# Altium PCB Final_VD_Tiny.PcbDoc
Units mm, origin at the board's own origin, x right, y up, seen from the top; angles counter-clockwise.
Board outline 34.21 x 13.79 mm, 2 copper layers (Top Layer, Bottom Layer), stack 1.671 mm thick; 35 components, 51 nets, 127 pads, 91 vias.
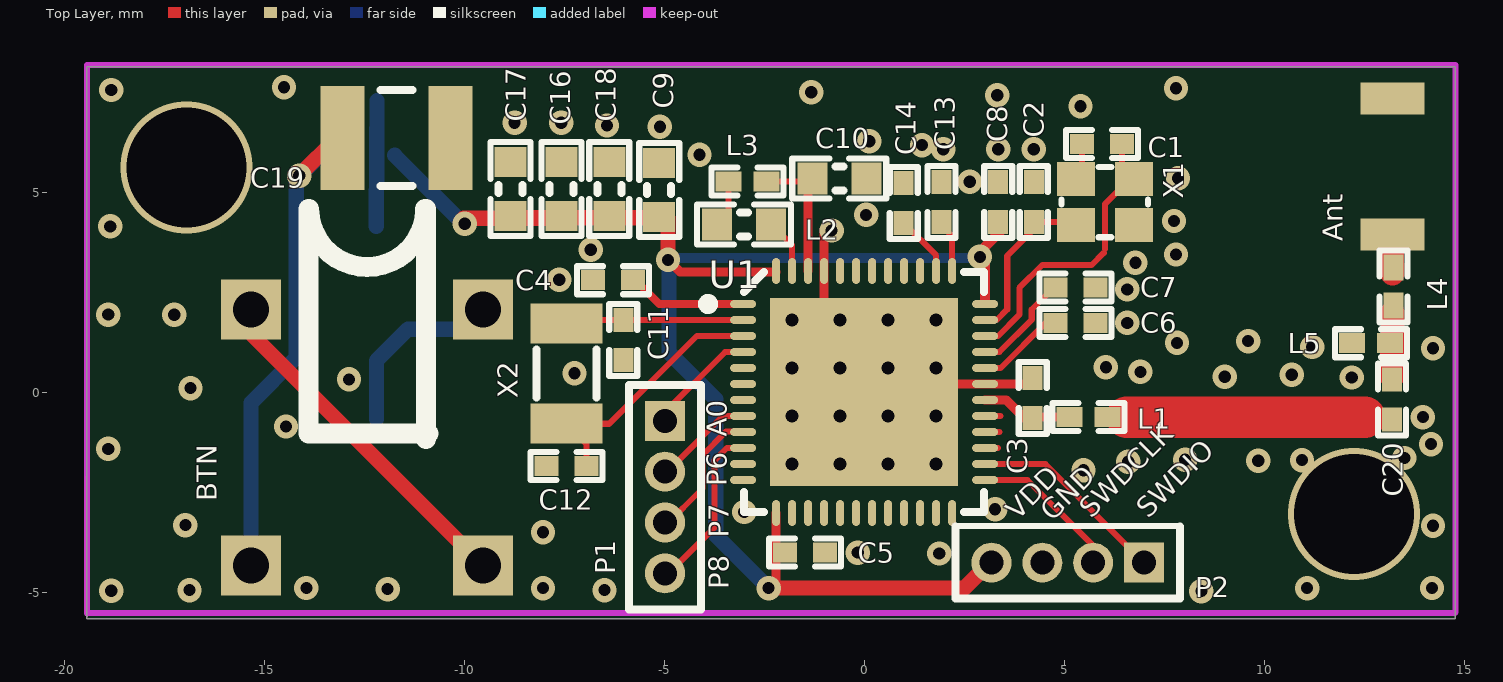
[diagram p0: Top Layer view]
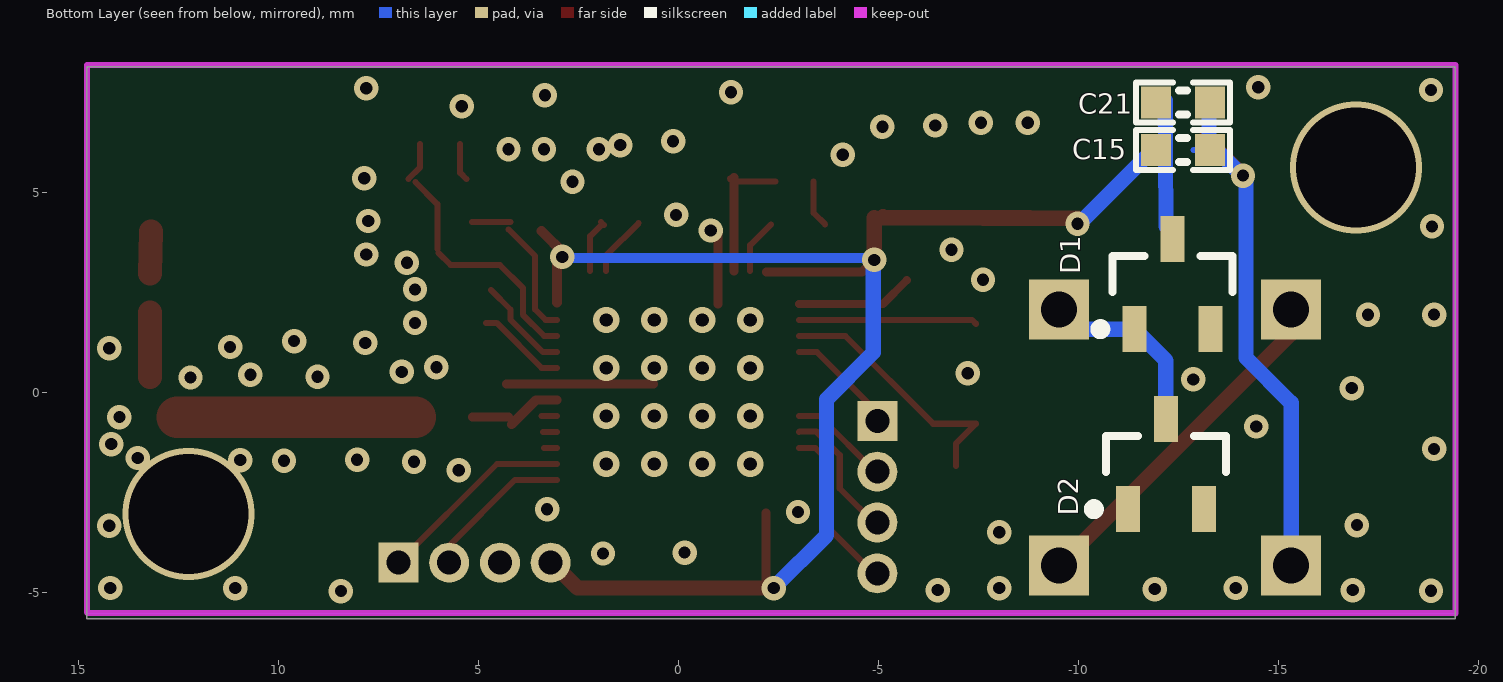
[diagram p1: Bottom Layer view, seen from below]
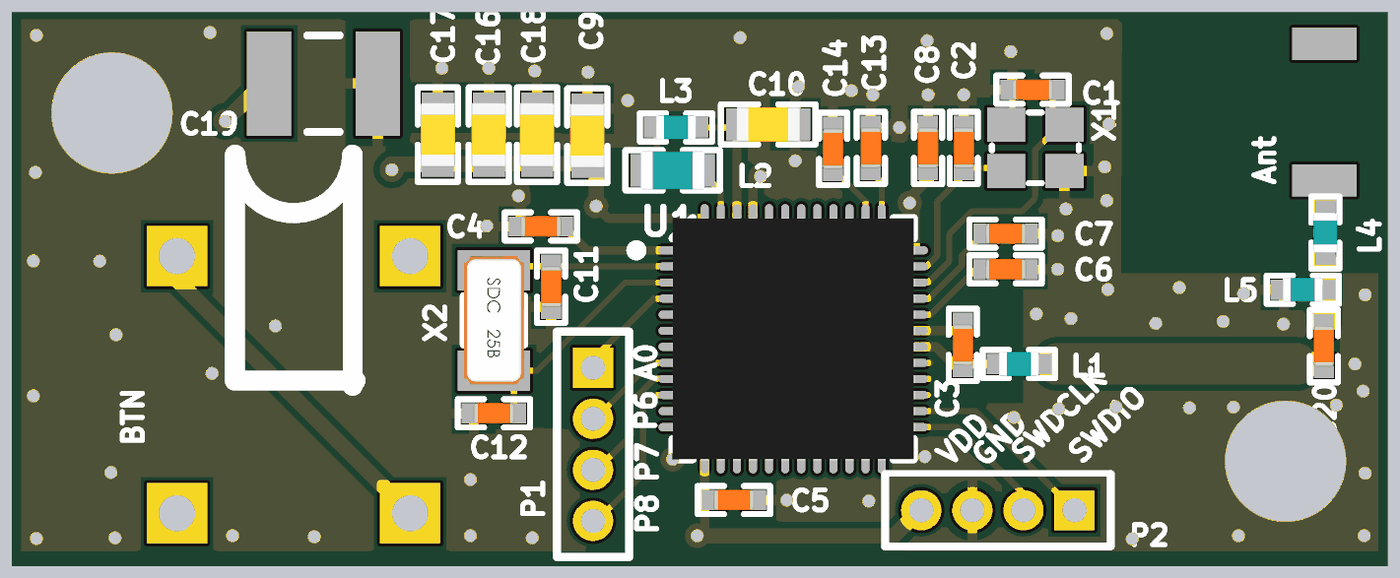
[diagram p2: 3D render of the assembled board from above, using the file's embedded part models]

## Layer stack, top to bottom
Top Solder: solder mask 0.0102, Solder Resist, Dk 3.5
Top Layer: signal copper 0.0356
Dielectric1: core 1.6002, FR-4, Dk 4.8
Bottom Layer: signal copper 0.0356
Bottom Solder: solder mask 0.0102, Solder Resist, Dk 3.5

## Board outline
-19.431,-5.664 14.783,-5.664 14.783,8.128 -19.431,8.128

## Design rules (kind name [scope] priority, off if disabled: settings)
Clearance Polygon_ANT [(InNamedPolygon('Top_Layer-GND')) or (InNamedPolygon('Bottom_Layer-GND')) vs InNet('RF')] p1: gap=0.127 ignorepadtopadclearanceinfootprint=FALSE except(0: Arc-Hole Track-Hole SMDPad-Hole THPad-Hole Via-Hole Fill-Hole Poly-Hole Region-Hole Text-Hole)
Clearance Polygon [(InNamedPolygon('Top_Layer-GND')) or (InNamedPolygon('Bottom_Layer-GND'))] p2: gap=0.254 ignorepadtopadclearanceinfootprint=FALSE except(0: Arc-Hole Track-Hole SMDPad-Hole THPad-Hole Via-Hole Fill-Hole Poly-Hole Region-Hole Text-Hole)
Clearance [All] p3: gap=0.152 ignorepadtopadclearanceinfootprint=FALSE except(0: Arc-Hole Track-Hole SMDPad-Hole THPad-Hole Via-Hole Fill-Hole Poly-Hole Region-Hole Text-Hole)
ComponentClearance [All] p1 off: gap=0.254 collisioncheckmode=3 verticalgap=0.254 showdistances=FALSE
FabricationTestPointUsage TestPointUsage [All] p1: valid=0 allowmultiple=FALSE
FabricationTestpoint Testpoint [All] p1: side=3 testpointundercomponent=TRUE minsize=1.016 maxsize=2.54 preferedsize=1.524 minholesize=0 maxholesize=1.016 preferedholesize=0.813 testpointgrid=0.025 allowsidetop=TRUE allowsidebottom=TRUE usegrid=TRUE gridtolerance=0
Height [All] p1 off: minheight=0 maxheight=25.4 prefheight=12.7
HoleSize [All] p1: absolutevalues=TRUE maxlimit=4.064 minlimit=0.305 maxpercent=80.000 minpercent=20.000
MinimumAnnularRing [All] p1 off: minimumring=0.152
PolygonConnect PolygonConnect_1 [isVia and innet(gnd)] p1: connectstyle=Direct reliefconductorwidth=0.254 reliefentries=4 polygonreliefangle="90 Angle" airgapwidth=0.254
PolygonConnect [All] p2: connectstyle=Relief reliefconductorwidth=0.254 reliefentries=4 polygonreliefangle="90 Angle" airgapwidth=0.254
RoutingVias [All] p1: holewidth=0.406 width=0.813 viastyle="Through Hole" minholewidth=0.254 minwidth=0.254 maxholewidth=0.711 maxwidth=1.27
SilkToSolderMaskClearance SilkscreenOverComponentPads [IsPad] p1: minsilkscreentomaskgap=0.254 clearancetoexposedcopper=TRUE
SolderMaskExpansion [All] p1: expansion=0.076
Width [All] p1: maxlimit=2.54 minlimit=0.152 preferedwidth=0.152
24 further rules are at their usual default settings.

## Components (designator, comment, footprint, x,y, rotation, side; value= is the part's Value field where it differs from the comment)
Ant "Antenna" antenne 13.208,5.639 r90 top (schematic designator E)
BTN "ZF_button" ZF-button -9.525,2.057 r270 top (schematic designator BTN_RB1)
C1 "12pF" CAPC1005X04L 5.952,6.198 r180 top
C2 "12pF" CAPC1005X04L 4.242,4.75 r90 top
C3 "0.8pF" CAPC1005X04L 4.216,-0.152 r270 top
C4 "100nF" CAPC1005X04L -6.274,2.794 r180 top
C5 "100nF" CAPC1005X04L -1.473,-4.013 r0 top
C6 "N.C." CAPC1005X04L 5.283,1.727 r180 top
C7 "100pF" CAPC1005X04L 5.283,2.616 r0 top
C8 "100nF" CAPC1005X04L 3.353,4.75 r90 top
C9 "4.7µF" CAPC1608X06L -5.121,5.055 r90 top
C10 "1.0µF" CAPC1608X06L -0.62,5.334 r180 top
C11 "12pF" CAPC1005X04L -6.02,1.295 r270 top
C12 "12pF" CAPC1005X04L -7.442,-1.854 r180 top
C13 "12pF" CAPC1005X04L 1.93,4.75 r90 top
C14 "12pF" CAPC1005X04L 0.991,4.724 r90 top
C15 "47µF" CAPC1608X06L -12.624,7.239 r0 bottom
C16 "10µF" CAPC1608X06L -7.569,5.08 r270 top
C17 "10µF" CAPC1608X06L -8.839,5.08 r270 top
C18 "10µF" CAPC1608X06L -6.37,5.08 r270 top
C19 "220µF" C1210 -11.684,6.35 r180 top
C20 "Cap" CAPC1005X04L 13.199,-0.184 r90 top value=12pF
C21 "47µF" CAPC1608X06L -12.624,6.045 r0 bottom
D1 "Diode 1N4004" SOT-23_N -12.355,2.695 r90 bottom
D2 "Diode 1N4004" SOT-23_N -12.192,-1.803 r90 bottom
L1 "3.9nH" INDC1005X04L 5.613,-0.627 r0 top
L2 "10µH" INDC1608X06L -2.997,4.191 r0 top
L3 "15nH" INDC1005X04L -2.913,5.258 r180 top
L4 "3.3nH" INDC1005X04L 13.233,2.642 r90 top value=3.9nH
L5 "2.7nH" INDC1005X04L 12.675,1.219 r180 top value=3.9nH
P1 "MHDR1X4" MHDR1X4 -4.978,-0.722 r270 top
P2 "MHDR1X4" MHDR1X4 6.996,-4.267 r180 top
U1 "nRF52832-QFAA" QFN40P600X600X90-48N 0,0 r0 top locked
X1 "32MHz" BT-XTAL_2016 6.02,4.75 r180 top
X2 "32.768kHz" XTAL_3215 -7.442,0.457 r270 top

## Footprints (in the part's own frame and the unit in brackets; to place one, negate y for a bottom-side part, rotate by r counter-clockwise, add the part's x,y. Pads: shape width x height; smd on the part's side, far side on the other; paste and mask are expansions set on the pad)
antenne [mm]
  rect 0.8x1.6 smd: 1(-1.7,0) 2(1.7,0)
BT-XTAL_2016 [mm] "Crystal 2.0 x 1.6 mm"
  rect 0.95x0.85 smd: 1(-0.725,-0.575) 2(0.725,-0.575) 3(0.725,0.575) 4(-0.725,0.575)
  silkscreen extent -1.08,-0.88 1.08,0.88
C1210 [mm] "Chip Capacitor, Body 3.2x2.5mm, IPC High Density"
  rect 1.1x2.6 smd: 1(-1.35,0) 2(1.35,0)
  silkscreen extent -0.4,-1.2 0.4,1.2, body extent -1.7,-1.35 1.7,1.35, height 1.3
CAPC1005X04L [mm] "Chip Capacitor, 2-Leads, Body 1.0x0.5mm, IPC High Density"
  rect 0.6x0.5 smd: 1(-0.5,0) 2(0.5,0)
  silkscreen extent -0.9,-0.35 0.9,0.35, body extent -0.51,-0.25 0.51,0.25, height 0.5
CAPC1608X06L [mm] "Chip Capacitor, 2-Leads, Body 1.6x0.8mm, IPC High Density"
  rect 0.75x0.8 smd: 1(-0.675,0) 2(0.675,0)
  silkscreen extent -1.17,-0.5 1.17,0.5, body extent -0.8,-0.43 0.8,0.43, height 0.8
INDC1005X04L [mm] "Chip Inductor, 2-Leads, Body 1.0x0.5mm, IPC High Density"
  rect 0.65x0.5 smd: 1(-0.475,0) 2(0.475,0)
  silkscreen extent -0.9,-0.35 0.9,0.35, body extent -0.5,-0.3 0.5,0.3, height 0.5
INDC1608X06L [mm]
  rect 0.75x0.8 smd: 1(-0.675,0) 2(0.675,0)
  silkscreen extent -1.17,-0.5 1.18,0.5, body extent -0.8,-0.48 0.8,0.48, height 0.8
MHDR1X4 [mm] "Connector; Header; 4 Position"
  rect 1x1 hole 0.6: 1(0,0)
  round 1 hole 0.6: 2(1.27,0) 3(2.54,0) 4(3.81,0)
  silkscreen extent -0.9,-0.9 4.71,0.9
QFN40P600X600X90-48N [mm] "QFN, 48-Leads, Body 6,0x6,0mm (max), Pitch 0,40mm, IPC Medium Density"
  oval 0.65x0.2 smd: 1(-3.025,2.2) 2(-3.025,1.8) 3(-3.025,1.4) 4(-3.025,1) 5(-3.025,0.6) 6(-3.025,0.2) 7(-3.025,-0.2) 8(-3.025,-0.6) 9(-3.025,-1) 10(-3.025,-1.4) 11(-3.025,-1.8) 12(-3.025,-2.2) 25(3.025,-2.2) 26(3.025,-1.8) 27(3.025,-1.4) 28(3.025,-1) 29(3.025,-0.6) 30(3.025,-0.2) 31(3.025,0.2) 32(3.025,0.6) 33(3.025,1) 34(3.025,1.4) 35(3.025,1.8) 36(3.025,2.2)
  oval 0.2x0.65 smd: 13(-2.2,-3.025) 14(-1.8,-3.025) 15(-1.4,-3.025) 16(-1,-3.025) 17(-0.6,-3.025) 18(-0.2,-3.025) 19(0.2,-3.025) 20(0.6,-3.025) 21(1,-3.025) 22(1.4,-3.025) 23(1.8,-3.025) 24(2.2,-3.025) 37(2.2,3.025) 38(1.8,3.025) 39(1.4,3.025) 40(1,3.025) 41(0.6,3.025) 42(0.2,3.025) 43(-0.2,3.025) 44(-0.6,3.025) 45(-1,3.025) 46(-1.4,3.025) 47(-1.8,3.025) 48(-2.2,3.025)
  rect 4.7x4.7 smd: 49(0,0)
  silkscreen extent -4.02,-3 3,3, body extent -3.02,-3.02 3.02,3.02, height 0.86
SOT-23_N [mm] "SOT23, 3-Leads, Body 2.9x1.3mm, Pitch 0.95mm, Lead Span 2.5mm, IPC Medium Density"
  rect 1.15x0.6 smd: 1(-1.125,0.95) 2(-1.125,-0.95) 3(1.125,0)
  silkscreen extent -1.25,-1.5 0.7,1.92, body extent -0.7,-1.5 0.7,1.5, height 1.1
XTAL_3215 [mm] "XTAL SMD 3.2 x 1.5 mm"
  rect 1x1.8 smd: 1(-1.25,0) 2(1.25,0)
  silkscreen extent -0.6,-0.75 0.6,0.75, body extent -1.6,-0.75 1.6,0.75, height 0.81
ZF-button [mm]
  rect 1.5x1.5 hole 0.9: 1(0,0) 2(0,-5.8) 3(6.4,-5.8) 4(6.4,0)
  silkscreen extent -2.52,-4.36 3.23,-1.36

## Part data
Ant: "Generic Antenna"
C1 C2 C11 C12 C13 C14: library part C0402-12p, "Capacitor, NP0, ±2%"
C3: library part C0402-0.8p, "Capacitor, NP0, ±5%"
C4 C5 C8: library part C0402-100n, "Capacitor, X7R, ±10%"
C6: library part C0402-N.C., "Not mounted"
C7: library part C0402-100p, "Capacitor, NP0, ±5%"
C9: library part C0603-4µ7, "Capacitor, X5R, ±10%"
C10: library part C0603-1µ0, "Capacitor, X7R, ±10%"
C15 C16 C17 C18 C19 C21: "Capacitor, X5R, ±10%", Part Number=C0603-4µ7
C20: "Capacitor"
D1 D2: "1 Amp General Purpose Rectifier"
L1 L4 L5: library part L0402-3n9, "High frequency chip inductor ±5%", Manufacturer=Murata, Manufacturer Part Number=LQP15MN3N9B02D, Supplier part number=490-1131-1-ND
L2: library part L0603-10µ, "Chip inductor, IDC,min = 50 mA, ±20%", 2nd source part number=178-6105, Manufacturer="Taiyo Yuden", Manufacturer Part Number=LBMF1608T100K, Supplier part number=587-1714-1-ND
L3: library part L0402-15n, "High frequency chip inductor ±10%", 2nd source part number=658-1328, Manufacturer="Taiyo Yuden", Manufacturer Part Number=HK100515NJ-T, Supplier part number=587-1521-1-ND
P1 P2: "Header, 4-Pin"
U1: "Multi-protocol Bluetooth Low Energy, ANT and 2.4GHz proprietary system-on-chip", Manufacturer="Nordic Semiconductor"
X1: library part XTAL_SMD2016_32MHz_8pF_General, "XTAL SMD 2016, 32MHz, Cl=8pF, Total Tol: ±40ppm"
X2: library part XTAL_SMD3215_32.768kHz_9pF_General, "XTAL SMD 3215, 32.768kHz, Cl=9pF, Total Tol: ±50ppm"

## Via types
v1: diameter 0.61, hole 0.305, Top Layer to Bottom Layer, tented both sides, 73 vias
v2: diameter 0.66, hole 0.33, Top Layer to Bottom Layer, tented both sides, 16 vias
v3: diameter 3.3, hole 3, Top Layer to Bottom Layer, tented both sides, 2 vias

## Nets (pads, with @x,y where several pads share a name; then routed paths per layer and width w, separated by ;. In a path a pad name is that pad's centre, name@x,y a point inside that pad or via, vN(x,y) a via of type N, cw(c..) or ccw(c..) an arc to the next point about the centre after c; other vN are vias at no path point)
DEC1: C4.1 U1.1 | length 2.9
  Top Layer w0.203: C4.1@-5.715,2.794 -5.121,2.2 U1.1
DEC2: C6.2 U1.32 | length 2.2
  Top Layer w0.152: U1.32 3.411,0.6 4.538,1.727 C6.2@4.801,1.727
DEC3: C7.1 U1.33 | length 2.4
  Top Layer w0.152: U1.33 3.38,1 4.191,1.811 4.191,2.062 C7.1@4.675,2.546
DEC4: C10.2 L3.1 U1.46 | length 3.4
  Top Layer w0.152: L3.1 -1.4,5.258 -1.372,5.258 C10.2
  Top Layer w0.229: U1.46 C10.2@-1.4,5.258 ; C10.2@-1.4,5.334 C10.2@-1.4,5.359
GND: C1.2 C2.2 C3.1 C4.2 C5.2 C6.1 C7.2 C8.2 C9.2 C10.1 C11.2 C12.2 C13.2 C14.2 C16.1 C17.1 C18.1 C19.1 D2.1 L5.2 P2.3 U1.31 U1.45 U1.49 X1.2 X1.4 | length 6.5
  Top Layer w0.152: X1.2 5.452,5.482 C1.2
  Top Layer w0.229: U1.49@-1,2.2 U1.45 v1@-1,4.064 ; U1.49@0.618,0.203 C3.1@4.293,0.203
  other v1: -18.821,-4.97 8.433,-4.978 -16.866,-4.953 -6.49,-4.953 -11.913,-4.928 -13.942,-4.901 -8.026,-4.902 11.074,-4.903 14.199,-4.901 1.88,-4.038 -0.16,-4.016 -8.026,-3.505 14.224,-3.345 -16.967,-3.327 -2.997,-3 3.277,-2.933 5.486,-1.956 6.604,-1.745 9.855,-1.719 8.026,-1.694 10.947,-1.703 13.508,-1.651 -18.898,-1.422 14.173,-1.303 -14.454,-0.864 13.97,-0.627 -16.84,0.098 -12.878,0.316 12.192,0.364 9.017,0.383 10.693,0.43 -7.239,0.471 6.909,0.502 6.045,0.618 14.224,1.093 11.201,1.126 7.823,1.227 9.601,1.272 6.579,1.727 -18.898,1.934 -17.247,1.93 6.579,2.565 -7.62,2.806 6.782,3.229 7.798,3.437 -6.833,3.556 -0.813,4.039 -18.847,4.14 7.747,4.275 0.051,4.428 2.642,5.258 7.849,5.342 -4.115,5.93 1.981,6.071 3.353,6.071 4.242,6.071 1.448,6.172 0.127,6.27 -5.105,6.633 -6.426,6.663 -8.738,6.731 -7.569,6.731 5.41,7.145 3.331,7.417 -1.321,7.493 -18.821,7.55 7.798,7.595 -14.503,7.62
  other v2: -1.8,-1.8 -0.6,-1.8 0.6,-1.8 1.8,-1.8 -1.8,-0.6 -0.6,-0.6 0.6,-0.6 1.8,-0.6 -1.8,0.6 -0.6,0.6 0.6,0.6 1.8,0.6 -1.8,1.8 -0.6,1.8 0.6,1.8 1.8,1.8
  other v3: 12.243,-3.048 -16.942,5.618
NetBTN_RB1_1: BTN.1 D1.1 D2.3 | length 4.6
  Bottom Layer w0.152: BTN.1@-9.957,1.57 BTN.1@-9.525,2.002
  Bottom Layer w0.381: D2.3 -12.192,0.783 D1.1 BTN.1@-9.957,1.57
NetBTN_RB1_2: BTN.2 BTN.4 | length 8.8
  Top Layer w0.152: BTN.2@-15.325,1.457 BTN.2
  Top Layer w0.381: BTN.2@-15.325,1.457 BTN.4
NetBTN_RB1_3: BTN.3 C15.1 C19.2 C21.1 | length 14.7
  Top Layer w0.152: C19.2@-13.183,6.35 C19.2
  Top Layer w0.381: v1(-14.122,5.41) C19.2@-13.183,6.35
  Bottom Layer w0.152: C21.1@-13.462,6.045 -13.268,6.045 -12.882,6.045
  Bottom Layer w0.381: BTN.3@-15.325,-4.398 -15.325,-0.271 -14.199,0.856 -14.199,5.309 C21.1@-13.462,6.045 ; C15.1@-13.284,7.341 -13.268,7.239 -13.268,6.045 C21.1@-13.268,5.893
NetC3_2: C3.2 L1.1 U1.30 | length 2.3
  Top Layer w0.152: C3.2 C3.2@4.242,-0.627
  Top Layer w0.229: U1.30 3.553,-0.2 C3.2@4.166,-0.813 ; C3.2@4.242,-0.627 L1.1
NetC20_2: C20.2 L4.1 L5.1 | length 2.3
  Top Layer w0.152: C20.2@13.199,0.373 L5.1@13.199,1.093
  Top Layer w0.6: C20.2@13.199,0.373 L4.1@13.208,1.989
NetE_1: Ant.1 L4.2 | length 1
  Top Layer w0.6: Ant.1@13.183,4.013 L4.2@13.208,2.966
NetL2_1: L2.1 L3.2 | length 1.2
  Top Layer w0.152: L2.1 -3.388,4.475 L3.2
NetL2_2: L2.2 U1.47 | length 1.4
  Top Layer w0.152: L2.2 -1.8,3.669 U1.47
P0.00/XL1: C11.1 U1.2 X2.1 | length 4.5
  Top Layer w0.152: X2.1 -7.349,1.8 U1.2
P0.01/XL2: C12.1 U1.3 X2.2 | length 6.6
  Top Layer w0.152: C12.1 -6.942,-1.293 X2.2 -6.372,-0.793 -4.18,1.4 U1.3
P0.02/AIN0: P1.1 U1.4 | length 2.8
  Top Layer w0.152: P1.1 -4.978,-0.508 -3.47,1 U1.4
P0.03/AIN1: U1.5
P0.04/AIN2: U1.6
P0.05/AIN3: U1.7
P0.06: P1.2 U1.8 | length 2.5
  Top Layer w0.152: P1.2 -4.925,-1.992 -3.533,-0.6 U1.8
P0.07: P1.3 U1.9 | length 3.4
  Top Layer w0.152: P1.3@-4.972,-3.345 -4.04,-2.413 -4.04,-1.577 -3.454,-0.991 -3.034,-0.991 U1.9
P0.08: P1.4 U1.10 | length 4.3
  Top Layer w0.152: P1.4@-4.972,-4.615 -3.735,-3.378 -3.735,-1.703 -3.432,-1.4 U1.10
P0.09: U1.11
P0.10: U1.12
P0.11: U1.14
P0.12: U1.15
P0.13: U1.16
P0.14: U1.17
P0.15: U1.18
P0.16: U1.19
P0.17: U1.20
P0.18: U1.21
P0.19: U1.22
P0.20: U1.23
P0.21: U1.24
P0.22: U1.27 | length 0.3
  Top Layer w0.152: U1.27 U1.27@3.349,-1.4
P0.23: U1.28 | length 0.4
  Top Layer w0.152: U1.28 3.38,-1
P0.24: U1.29 | length 0.4
  Top Layer w0.152: U1.29 3.411,-0.6
P0.25: C13.1 U1.37 | length 1.4
  Top Layer w0.152: C13.1 1.854,4.173 1.923,4.173 2.2,3.896 U1.37
P0.26: C14.1 U1.38 | length 1.5
  Top Layer w0.152: C14.1 1.8,3.415 U1.38
P0.27: U1.39
P0.28/AIN4: U1.40
P0.29/AIN5: U1.41
P0.30/AIN6: U1.42
P0.31/AIN7: U1.43
RF: C20.1 L1.2 | length 6
  Top Layer w1.035: 6.571,-0.627 12.522,-0.627
SWDCLK: P2.2 U1.25 | length 3.8
  Top Layer w0.152: U1.25 4.08,-2.2 5.726,-3.846 P2.2
SWDIO: P2.1 U1.26 | length 5
  Top Layer w0.152: U1.26 4.529,-1.8 P2.1
VDD_NRF: C5.1 C8.1 C9.1 C15.2 C16.2 C17.2 C18.2 C21.2 D1.3 P2.4 U1.13 U1.36 U1.48 | length 42.5
  Top Layer w0.152: C17.2 C17.2@-8.788,4.354 ; C16.2@-7.631,4.343 -7.62,4.354 C16.2 ; C9.1@-4.953,4.405 C9.1@-4.902,4.354
  Top Layer w0.229: v1(-4.902,3.302) -4.6,3 U1.48@-2.21,3 ; v1(-2.388,-4.902) -2.2,-4.715 U1.13
  Top Layer w0.254: v1@2.837,3.446 C8.1@3.416,4.026 ; U1.36@3.025,2.235 v1@3.025,3.302
  Top Layer w0.381: v1@-10.008,4.343 C16.2@-7.631,4.343 ; C17.2@-8.788,4.354 -7.62,4.354 -6.37,4.354 -5.146,4.354 C9.1 ; v1(-4.902,3.302) C9.1@-4.902,4.354 ; v1(-2.388,-4.902) 2.515,-4.902 P2.4@3.175,-4.242
  Bottom Layer w0.254: v1@-5.006,3.353 v1@2.769,3.353
  Bottom Layer w0.381: D1.3@-12.195,4.144 -12.183,6.047 -12.175,7.24 C15.2@-12.175,7.291 ; C21.2@-11.733,5.917 -9.982,4.166 v1(-9.982,4.205) ; v1@-4.877,3.277 -4.877,0.986 -3.707,-0.184 -3.707,-3.583 v1(-2.388,-4.902)
  other v1: 2.896,3.378
XC1: C1.1 U1.34 X1.1 | length 7.1
  Top Layer w0.152: U1.34 3.349,1.4 3.883,1.934 3.883,2.603 4.456,3.175 5.69,3.175 5.994,3.48 ; 6.02,3.581 6.02,4.699 X1.1@6.571,5.25 ; C1.1 6.452,5.618 X1.1
XC2: C2.1 U1.35 X1.3 | length 3.9
  Top Layer w0.152: U1.35 3.315,1.8 3.579,2.064 3.579,3.401 C2.1@4.242,4.064 ; C2.1@4.191,4.25 C2.1 X1.3@5.148,4.25
pads on no net: Ant.2 D1.2 D2.2 U1.44

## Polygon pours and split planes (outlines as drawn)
GND on Top Layer "Top Layer-GND" (solid, shelved, pour order 1004): -19.431,8.153 14.783,8.153 14.783,-5.512 14.757,-5.537 -19.456,-5.537
GND on Bottom Layer "Bottom Layer-GND" (solid, shelved, pour order 1006): -19.431,8.103 14.783,8.103 14.783,-5.537 -19.431,-5.537

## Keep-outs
Keep-Out Layer:
  lines w0.152: -19.431,8.153 -19.431,-5.537 -19.418,-5.525 14.77,-5.525 14.783,-5.512 14.783,8.179 -19.431,8.179

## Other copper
Top Layer:
  pour cut-out: -5.006,-5.322 -4.993,-5.309 -2.388,-5.309 -2.388,-2.412 -2.413,-2.388 -2.438,-2.413 -3.52,-2.413 -3.52,-3.375 -4.437,-4.293 -4.513,-4.293
  pour cut-out: -6.579,-2.204 -5.564,-2.204 -5.512,-2.257
  pour cut-out: -4.671,4.75 -3.881,4.75 -3.797,4.666
  pour cut-out: -6.579,3.937 -6.502,3.861 -6.502,3.144
  pour cut-out: 2.298,4.923 2.37,4.851 2.921,4.851
  pour cut-out: 8.179,8.128 14.681,8.128 14.681,1.626 8.153,1.626
  pour cut-out: 14.681,8.128
  pour cut-out: 5.715,-1.6 2.972,-1.6 2.972,1.295 5.715,1.295
Bottom Layer:
  pour cut-out: -14.3,0.737 -14.574,0.737 -15.164,0.147
  pour cut-out: -10.389,0.813 -10.617,0.584 -14.58,0.584 -14.58,4.744 -13.981,5.342 -12.99,5.342 -12.548,4.899 -12.447,4.999 -10.185,4.999
  pour cut-out: -10.998,1
  pour cut-out: -4.75,-0.239 -4.627,-0.117 -4.269,-0.117 -3.954,-0.432 -4.013,-0.491 -4.013,-3.704 -2.54,-5.177 -2.591,-5.228 -2.591,-5.448 -4.877,-5.448
  pour cut-out: 14.668,8.128 8.166,8.128 8.166,1.626 14.694,1.626

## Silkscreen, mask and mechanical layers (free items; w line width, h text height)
Top Overlay:
  lines w0.152: 2.311,-3.348 7.857,-3.348
  text "A0" at -3.429,-1.118 h0.5 r90
  text "P6" at -3.432,-2.358 h0.5 r90
  text "SWDCLK" at 5.677,-3.175 h0.5 r45
  text "SWDIO" at 7.1,-3.175 h0.5 r45
  text "VDD" at 3.835,-3.226 h0.5 r45
  text "GND" at 4.699,-3.251 h0.5 r45
  text "P7" at -3.388,-3.642 h0.5 r90
  text "P8" at -3.388,-4.928 h0.5 r90
Mechanical 1:
  pour cut-out: -3.785,5.563 -9.423,5.563 -9.339,5.478 -9.339,4.826 -3.893,4.826 -3.81,4.743
  pour cut-out: -4.671,4.801
  pour cut-out: -6.426,3.175 -6.553,3.302 -6.553,3.988
Mechanical 3:
  text "EHSB" at 10.592,-3.2 h3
